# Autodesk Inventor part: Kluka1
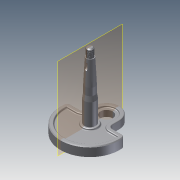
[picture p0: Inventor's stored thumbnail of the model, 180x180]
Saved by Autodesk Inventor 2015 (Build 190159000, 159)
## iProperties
Created: 2012-07
Part Number: Kluka1
Document SubType Name: Modeling
Designer: Michman
Material: Všeobecné
Density: 1 g/cm^3
Appearance: Výchozí
Author: Michman
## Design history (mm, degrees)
sketch "Náčrt1"
  geometry: L1 (16.943, 22.658)-(16.943, 13.658); L2 (-17.057, 22.658)-(-17.057, 13.658); L3 (-33.924, 8.658)-(-22.057, 8.658); L4 (21.943, 8.658)-(33.811, 8.658); C1 r 8.05 at (-0.057, 22.658); A1 r 39 centre (-0.057, 0.658) between (-38.905, 4.1) and (38.791, 4.1); A2 r 17 centre (-0.057, 22.658) between (16.943, 22.658) and (-17.057, 22.658); A3 r 5 centre (-33.924, 3.658) between (-33.924, 8.658) and (-38.905, 4.1); A4 r 5 centre (-22.057, 13.658) between (-22.057, 8.658) and (-17.057, 13.658); A5 r 5 centre (21.943, 13.658) between (16.943, 13.658) and (21.943, 8.658); A6 r 5 centre (33.811, 3.658) between (38.791, 4.1) and (33.811, 8.658)
  constraints: 12 point on circle, 9 tangent, 8 end point, 7 centre point, 3 equal radius, 2 horizontal, 2 perpendicular, 1 coincident
  dimensions: "d0" = 78 diameter of A1; "d1" = 34 diameter of A2; "d2" = 22 distance of A1.centre A2.centre; "d4" = 5 radius of A3; "d5" = 16.1 diameter of C1
extrude "Vysunutí1" new body sketch "Náčrt1" distance "d6" = 10; taper "d7" = 0 deg
chamfer "Zkosení1" distance "d8" = 1; stored, may be unused: second distance "d9" = 2, angle "d10" = 45 deg
sketch "Náčrt2"
  geometry: L1 (-37.342, 10)-(7.156, 10) reference; L2 (39.658, 0)-(39.658, 10) reference; L3 (0.658, 12.255)-(0.658, 48.902); L4 (8.158, 10)-(8.158, 38.573); L5 (8.158, 38.573)-(7.158, 44.94); L6 (7.158, 44.94)-(7.158, 54.562); L7 (7.158, 54.562)-(5.591, 86.046); L8 (5.591, 86.046)-(4.658, 86); L9 (4.658, 86)-(4.658, 97); L10 (4.658, 97)-(2.519, 97); L11 (-38.342, 0)-(-38.342, 9) reference; L12 (2.519, 97)-(0.658, 97); L13 (0.658, 48.902)-(0.658, 97); L14 (0.658, 12.255)-(0.658, 10); L15 (7.156, 10)-(8.158, 10)
  constraints: 24 end point, 6 perpendicular, 4 parallel, 2 point on line
  dimensions: "d11" = 7.5 distance between parallel lines of L4 L3; "d12" = 39 distance between parallel lines of L3 L2; "d13" = 28.57289 distance of L4.start L4.end; "d14" = 87 distance between parallel lines of L10 L1; "d15" = 76 distance from line of L1 L8.end; "d16" = 6.5 distance from line of L3 L5.end; "d17" = 2.85 deg angle of L7 L6; "d18" = 4 distance between parallel lines of L3 L9
revolve "Rotace1" sketch "Náčrt2" stored, may be unused: angle "d19" = 90 deg
feature "Závit1" dims "d20" = 10, "d21" = 0
chamfer "Zkosení2" distance "d22" = 1.2; stored, may be unused: second distance "d23" = 2, angle "d24" = 45 deg
sketch "Náčrt7"
  geometry: L1 (-5.842, 54.562)-(-5.842, 44.94) reference; L2 (-4.274, 86.046)-(5.591, 86.046) reference; C1 r 5 at (-6.942, 77.046)
  constraints: 1 centre point
  dimensions: "d37" = 10 diameter of C1; "d38" = 1.1 distance from line of L1 C1.centre; "d39" = 9 distance from line of L2 C1.centre
extrude "Vysunutí6" cut sketch "Náčrt7" stored distance "d40" = 3; taper "d41" = 0 deg
sketch "Náčrt8"
  geometry: L1 (-33.811, 8.658)-(-21.943, 8.658) reference; L2 (22.057, 8.658)-(33.924, 8.658) reference; A1 r 5 centre (-33.811, 3.658) between (-33.811, 8.658) and (-38.791, 4.1) reference; A2 r 39 centre (0.057, 0.658) between (-38.791, 4.1) and (38.905, 4.1) reference; A3 r 5 centre (33.924, 3.658) between (38.905, 4.1) and (33.924, 8.658) reference; A4 r 19.286 centre (0.057, 0.658) between (-18.79, 4.748) and (18.904, 4.748); A5 r 3.226 centre (-21.943, 5.432) between (-18.79, 4.748) and (-21.943, 8.658); A6 r 3.226 centre (22.057, 5.432) between (22.057, 8.658) and (18.904, 4.748)
  constraints: 6 point on circle, 3 centre point, 2 tangent, 1 coincident
extrude "Vysunutí7" join sketch "Náčrt8" distance "d42" = 2; taper "d43" = 0 deg
fillet "Zaoblení1" dims "d44" = 0.5
fillet "Zaoblení2" dims "d45" = 1
sketch "Náčrt9"
  geometry: L1 (21.943, 7.658)-(33.811, 7.658) reference; L2 (15.943, 22.658)-(15.943, 13.658) reference; L3 (-16.057, 13.658)-(-16.057, 22.658) reference; L4 (-33.924, 7.658)-(-22.057, 7.658) reference; L5 (11.943, 22.658)-(11.943, 13.658); L6 (21.943, 3.658)-(33.811, 3.658); L7 (-33.924, 3.658)-(-22.057, 3.658); L8 (-12.057, 13.658)-(-12.057, 22.658); C1 r 8.05 at (-0.057, 22.658) reference; C2 r 7.5 at (0, 0.658) reference; C3 r 10 at (0, 0.658); A1 r 4 centre (33.811, 3.658) between (37.795, 4.011) and (33.811, 7.658) reference; A2 r 6 centre (21.943, 13.658) between (15.943, 13.658) and (21.943, 7.658) reference; A3 r 16 centre (-0.057, 22.658) between (15.943, 22.658) and (-16.057, 22.658) reference; A4 r 6 centre (-22.057, 13.658) between (-22.057, 7.658) and (-16.057, 13.658) reference; A5 r 4 centre (-33.924, 3.658) between (-33.924, 7.658) and (-37.909, 4.011) reference; A6 r 38 centre (-0.057, 0.658) between (-37.909, 4.011) and (37.795, 4.011) reference; A7 r 12 centre (-0.057, 22.658) between (11.943, 22.658) and (-12.057, 22.658); A8 r 10 centre (21.943, 13.658) between (11.943, 13.658) and (21.943, 3.658); A9 r 34 centre (-0.057, 0.658) between (-33.924, 3.658) and (33.811, 3.658); A10 r 0 centre (-33.924, 3.658) between (-33.924, 3.658) and (-33.924, 3.658); A11 r 10 centre (-22.057, 13.658) between (-22.057, 3.658) and (-12.057, 13.658); 1 further point
  constraints: 8 end point, 8 point on circle, 6 centre point, 2 coincident with centre, 1 coincident, 13 other
  dimensions: "d46" = 4 radial gap between concentric circles of A6 A9; "d47" = 20 diameter of C3
extrude "Vysunutí8" cut sketch "Náčrt9" distance "d48" = 2; taper "d49" = 0 deg
fillet "Zaoblení3" dims "d50" = 1
node "Těleso1"
node "Objemová tělesa"
node "Povrchová tělesa"
other parameters: "d3" = 8
